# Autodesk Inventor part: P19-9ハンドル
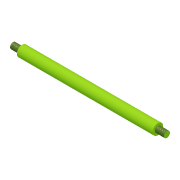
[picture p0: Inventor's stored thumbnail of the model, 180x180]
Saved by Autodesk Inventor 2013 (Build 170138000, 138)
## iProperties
Created: 2008-07
Part Number: P19-9ハンドル
Document SubType Name: Modeling
Designer: y-shimohigashi
Density: 1 g/cm^3
Stock Number: P19-9ハンドル
Material: 一般
Author: y-shimohigashi
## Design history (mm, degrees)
sketch "スケッチ1"
  geometry: L1 (-102, 0)-(102, 0); L2 (-102, 0)-(-102, 4); L3 (-102, 4)-(-90, 4); L4 (-90, 4)-(-90, 7); L5 (-90, 7)-(90, 7); L6 (90, 7)-(90, 4); L7 (90, 4)-(102, 4); L8 (102, 4)-(102, 0); 2 further points
  constraints: 16 end point, 4 parallel, 3 collinear, 2 perpendicular, 1 coincident, 1 horizontal, 1 midpoint
  dimensions: "d0" = 7 distance between parallel lines of L1 L5; "d1" = 4 distance of L7.end L1.end; "d2" = 180 distance of L4.end L5.end; "d3" = 12 distance of L6.end L7.end
revolve "回転1" sketch "スケッチ1" stored, may be unused: angle "d4" = 90 deg
feature "ねじ1" dims "d5" = 10, "d6" = 0
feature "ねじ2" dims "d7" = 10, "d8" = 0
node "ソリッド1"
node "ソリッド ボディ"
node "サーフェス ボディ"
